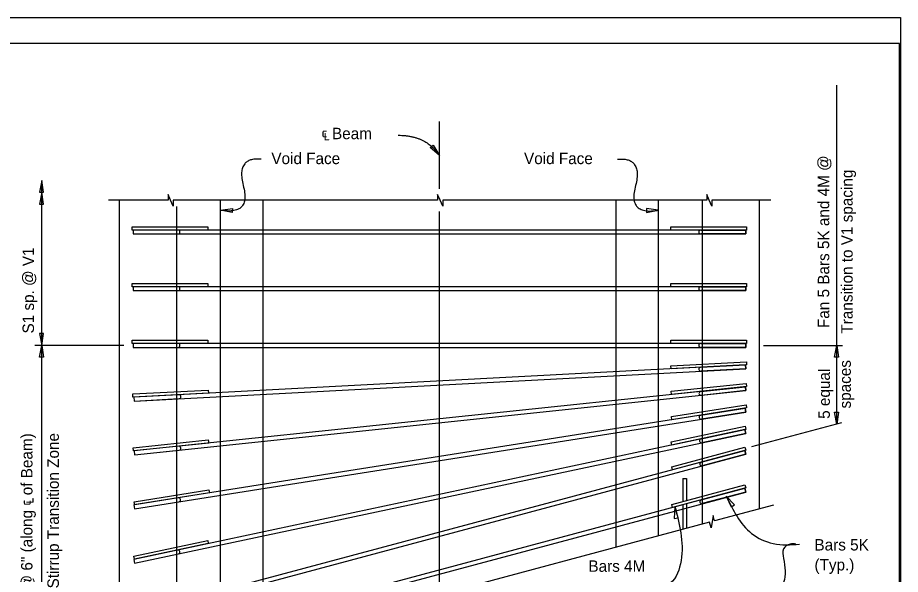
# Model space of a CAD drawing. Extents: x 0 to 30.8, y 0 to 19.8.
# Drawn here: x 19.12 to 30.8, y 12.43 to 19.8 of the extents above; entities that cross this region are included whole.
import ezdxf

# ---------------------------------------------------------------- set-up
doc = ezdxf.new("R2010")
doc.units = 0
for name, color, linetype in [('ActivePts-ConstElements', 7, 'Continuous'), ('BeamConc', 7, 'Continuous'), ('BeamConc_h', 7, 'Continuous'), ('CL_Major', 7, 'Continuous'), ('Dimension', 7, 'Continuous'), ('Miscellaneous1', 7, 'Continuous'), ('Rebar', 7, 'Continuous'), ('Rebar_h', 7, 'Continuous'), ('TextStructures', 7, 'Continuous')]:
    doc.layers.add(name, color=color, linetype=linetype)

msp = doc.modelspace()

# ---------------------------------------------------------------- linework, layer by layer
at = {"layer": 'ActivePts-ConstElements'}
msp.add_lwpolyline([(0, 0), (30.788, 0), (30.788, 19.46), (0, 19.46)], close=True, dxfattribs=at)
at = {"layer": 'BeamConc'}
for p, q in [((20.473, 11.032), (20.473, 17.385)), ((21.807, 11.389), (21.807, 17.385)), ((27.598, 17.385), (27.598, 12.947)), ((28.932, 17.385), (28.932, 13.298))]:
    msp.add_line(p, q, dxfattribs=at)
at = {"layer": 'BeamConc_h'}
for p, q in [((21.223, 17.303), (21.223, 11.233)), ((22.369, 17.385), (22.369, 11.54)), ((27.036, 17.385), (27.036, 12.79)), ((28.182, 13.097), (28.182, 17.385))]:
    msp.add_line(p, q, dxfattribs=at)
at = {"layer": 'CL_Major'}
for p, q in [((24.702, 17.537), (24.702, 18.427)), ((24.702, 12.302), (24.702, 17.235))]:
    msp.add_line(p, q, dxfattribs=at)
at = {"layer": 'Dimension'}
for p, q in [((29.958, 14.423), (29.958, 18.908)), ((20.527, 15.464), (19.35, 15.464)), ((28.989, 15.464), (30.034, 15.464)), ((30.022, 14.441), (28.83, 14.121))]:
    msp.add_line(p, q, dxfattribs=at)
for points in [[(24.702, 17.978), (24.581, 18.08), (24.621, 18.114)], [(19.442, 17.646), (19.415, 17.49), (19.468, 17.49)], [(19.442, 17.49), (19.415, 17.334), (19.468, 17.334)], [(21.807, 17.252), (21.964, 17.274), (21.962, 17.221)], [(27.598, 17.252), (27.441, 17.274), (27.443, 17.221)], [(19.442, 15.464), (19.468, 15.62), (19.415, 15.62)], [(19.442, 15.464), (19.468, 15.308), (19.415, 15.308)], [(29.958, 15.464), (29.984, 15.308), (29.931, 15.308)], [(29.958, 14.423), (29.931, 14.58), (29.984, 14.58)], [(28.496, 13.47), (28.562, 13.326), (28.606, 13.356)], [(27.817, 13.333), (27.809, 13.175), (27.861, 13.181)]]:
    msp.add_lwpolyline(points, close=True, dxfattribs=at)
for points in [[(19.442, 11.509), (19.442, 17.646)], [(21.694, 17.385), (21.182, 17.385), (21.182, 17.307), (21.148, 17.385), (21.114, 17.462), (21.114, 17.385), (20.325, 17.385)], [(27.522, 17.385), (24.746, 17.385), (24.746, 17.307), (24.712, 17.385), (24.678, 17.462), (24.678, 17.385), (21.694, 17.385)], [(29.086, 17.385), (28.307, 17.385), (28.307, 17.307), (28.273, 17.385), (28.239, 17.462), (28.239, 17.385), (27.522, 17.385)], [(29.121, 13.349), (28.342, 13.141), (28.322, 13.215), (28.31, 13.132), (28.297, 13.048), (28.277, 13.123), (26.782, 12.723)], [(26.782, 12.723), (24.745, 12.177), (24.725, 12.252), (24.713, 12.168), (24.705, 12.116)]]:
    msp.add_lwpolyline(points, dxfattribs=at)
for points in [[(24.159, 18.244), (24.523, 18.244), (24.702, 17.979)], [(22.345, 17.927), (22.008, 17.958), (22.211, 17.182), (21.807, 17.252)], [(27.06, 17.927), (27.397, 17.958), (27.194, 17.182), (27.598, 17.252)]]:
    msp.add_open_spline(points, degree=2, dxfattribs=at)
for points in [[(28.496, 13.47), (28.833, 12.976), (29.118, 12.842), (29.467, 12.833)], [(27.817, 13.338), (27.899, 12.616), (27.755, 12.319), (27.582, 12.253), (27.422, 12.253)], [(29.419, 12.835), (29.343, 12.835), (29.255, 12.772), (29.255, 12.645), (29.255, 12.328), (29.157, 12.174), (29.014, 12.076), (28.873, 12.034), (28.735, 11.996)]]:
    msp.add_spline(points, degree=3, dxfattribs=at)
at = {"layer": 'Miscellaneous1'}
msp.add_lwpolyline([(0, 19.8), (30.8, 19.8), (30.8, 0), (0, 0)], close=True, dxfattribs=at)
at = {"layer": 'Rebar'}
for p, q in [((20.64, 17.032), (21.64, 17.032)), ((20.64, 16.99), (20.64, 17.032)), ((21.64, 16.99), (20.64, 16.99)), ((21.245, 16.99), (20.651, 16.99)), ((20.651, 16.99), (20.651, 16.938)), ((20.651, 16.938), (21.245, 16.938)), ((21.64, 17.032), (21.64, 16.99)), ((27.765, 17.032), (28.765, 17.032)), ((27.765, 16.99), (27.765, 17.032)), ((28.765, 16.99), (27.765, 16.99)), ((28.16, 16.99), (28.754, 16.99)), ((28.754, 16.938), (28.16, 16.938)), ((28.754, 16.99), (28.754, 16.938)), ((28.765, 17.032), (28.765, 16.99)), ((20.64, 16.282), (21.64, 16.282)), ((20.64, 16.24), (20.64, 16.282)), ((21.64, 16.24), (20.64, 16.24)), ((21.245, 16.24), (20.651, 16.24)), ((20.651, 16.24), (20.651, 16.188)), ((21.64, 16.282), (21.64, 16.24)), ((27.765, 16.282), (28.765, 16.282)), ((27.765, 16.24), (27.765, 16.282)), ((28.765, 16.24), (27.765, 16.24)), ((28.16, 16.24), (28.754, 16.24)), ((28.754, 16.24), (28.754, 16.188)), ((28.765, 16.282), (28.765, 16.24)), ((20.651, 16.188), (21.245, 16.188)), ((28.754, 16.188), (28.16, 16.188)), ((20.64, 15.532), (21.64, 15.532)), ((20.64, 15.49), (20.64, 15.532)), ((21.64, 15.532), (21.64, 15.49)), ((27.765, 15.532), (28.765, 15.532)), ((27.765, 15.49), (27.765, 15.532)), ((28.765, 15.532), (28.765, 15.49)), ((21.64, 15.49), (20.64, 15.49)), ((21.245, 15.49), (20.651, 15.49)), ((20.651, 15.49), (20.651, 15.438)), ((20.651, 15.438), (21.245, 15.438)), ((28.765, 15.49), (27.765, 15.49)), ((28.16, 15.49), (28.754, 15.49)), ((28.754, 15.438), (28.16, 15.438)), ((28.754, 15.49), (28.754, 15.438)), ((27.765, 15.195), (28.764, 15.247)), ((27.767, 15.153), (27.765, 15.195)), ((28.766, 15.205), (27.767, 15.153)), ((28.16, 15.174), (28.753, 15.205)), ((28.753, 15.205), (28.756, 15.153)), ((28.764, 15.247), (28.766, 15.205)), ((28.756, 15.153), (28.163, 15.122)), ((27.767, 14.856), (28.761, 14.96)), ((28.761, 14.96), (28.766, 14.919)), ((20.646, 14.821), (21.645, 14.873)), ((21.647, 14.831), (20.648, 14.779)), ((21.645, 14.873), (21.647, 14.831)), ((27.771, 14.814), (27.767, 14.856)), ((28.766, 14.919), (27.771, 14.814)), ((28.159, 14.855), (28.75, 14.917)), ((28.755, 14.865), (28.165, 14.803)), ((28.75, 14.917), (28.755, 14.865)), ((20.648, 14.779), (20.646, 14.821)), ((21.256, 14.811), (20.663, 14.78)), ((20.663, 14.78), (20.665, 14.728)), ((20.665, 14.728), (21.259, 14.759)), ((27.771, 14.521), (28.759, 14.677)), ((28.765, 14.636), (27.778, 14.48)), ((28.16, 14.54), (28.747, 14.633)), ((28.747, 14.633), (28.755, 14.582)), ((28.759, 14.677), (28.765, 14.636)), ((27.778, 14.48), (27.771, 14.521)), ((28.755, 14.582), (28.168, 14.489)), ((27.77, 14.186), (28.749, 14.394)), ((28.749, 14.394), (28.757, 14.353)), ((28.757, 14.353), (27.779, 14.145)), ((28.164, 14.227), (28.745, 14.351)), ((28.756, 14.3), (28.175, 14.176)), ((28.745, 14.351), (28.756, 14.3)), ((20.652, 14.109), (21.646, 14.214)), ((21.651, 14.172), (20.656, 14.068)), ((21.254, 14.129), (20.664, 14.067)), ((21.646, 14.214), (21.651, 14.172)), ((27.779, 14.145), (27.77, 14.186)), ((20.656, 14.068), (20.652, 14.109)), ((20.664, 14.067), (20.669, 14.015)), ((20.669, 14.015), (21.26, 14.077)), ((27.777, 13.859), (28.743, 14.118)), ((28.754, 14.078), (27.788, 13.819)), ((28.167, 13.92), (28.741, 14.074)), ((28.754, 14.024), (28.18, 13.87)), ((28.741, 14.074), (28.754, 14.024)), ((28.743, 14.118), (28.754, 14.078)), ((27.788, 13.819), (27.777, 13.859)), ((27.921, 13.703), (27.973, 13.703)), ((27.921, 13.703), (27.921, 13.398)), ((27.973, 13.703), (27.973, 13.412)), ((20.665, 13.396), (21.653, 13.552)), ((21.653, 13.552), (21.66, 13.511)), ((27.777, 13.359), (28.743, 13.618)), ((28.754, 13.578), (27.788, 13.319)), ((28.167, 13.42), (28.741, 13.574)), ((28.741, 13.574), (28.754, 13.524)), ((28.743, 13.618), (28.754, 13.578)), ((21.249, 13.446), (20.662, 13.353)), ((21.66, 13.511), (20.672, 13.354)), ((28.754, 13.524), (28.18, 13.37)), ((20.662, 13.353), (20.671, 13.301)), ((20.672, 13.354), (20.665, 13.396)), ((20.671, 13.301), (21.257, 13.394)), ((27.788, 13.319), (27.777, 13.359)), ((27.921, 13.354), (27.921, 13.028)), ((27.973, 13.368), (27.973, 13.042)), ((20.659, 12.675), (21.638, 12.883)), ((21.638, 12.883), (21.646, 12.842)), ((21.24, 12.755), (20.659, 12.632)), ((21.646, 12.842), (20.668, 12.634)), ((20.668, 12.634), (20.659, 12.675)), ((20.659, 12.632), (20.67, 12.581)), ((20.67, 12.581), (21.251, 12.704))]:
    msp.add_line(p, q, dxfattribs=at)
for centre, start, end in [((21.245, 16.964), 270, 90), ((28.16, 16.964), 90, 270), ((21.245, 16.214), 270, 90), ((28.16, 16.214), 90, 270), ((21.245, 15.464), 270, 90), ((28.16, 15.464), 90, 270), ((28.161, 15.148), 93, 273), ((28.162, 14.829), 96, 276), ((21.257, 14.785), 273, 93), ((28.164, 14.515), 99, 279), ((21.257, 14.103), 276, 96), ((28.169, 14.202), 102, 282), ((28.174, 13.895), 105, 285), ((21.253, 13.42), 279, 99), ((28.174, 13.395), 105, 285), ((21.245, 12.73), 282, 102)]:
    msp.add_arc(centre, 0.026, start, end, dxfattribs=at)
at = {"layer": 'Rebar_h'}
for points in [[(28.754, 16.99), (20.651, 16.99), (20.651, 16.938), (28.754, 16.938)], [(28.754, 16.24), (20.651, 16.24), (20.651, 16.188), (28.754, 16.188)], [(28.754, 15.49), (20.651, 15.49), (20.651, 15.438), (28.754, 15.438)], [(28.753, 15.205), (20.663, 14.78), (20.665, 14.728), (28.756, 15.153)], [(28.75, 14.917), (20.664, 14.067), (20.669, 14.015), (28.755, 14.865)], [(28.747, 14.633), (20.662, 13.353), (20.671, 13.301), (28.755, 14.582)], [(28.745, 14.351), (20.659, 12.632), (20.67, 12.581), (28.756, 14.3)], [(28.741, 14.074), (20.651, 11.906), (20.665, 11.856), (28.754, 14.024)], [(28.741, 13.574), (20.651, 11.406), (20.665, 11.356), (28.754, 13.524)]]:
    msp.add_lwpolyline(points, close=True, dxfattribs=at)

# ---------------------------------------------------------------- texts
at = {"layer": 'Dimension'}
for s, p in [('Bars 5K', (29.664, 12.75)), ('Bars 4M ', (26.674, 12.468)), ('(Typ.)', (29.664, 12.486))]:
    msp.add_text(s, height=0.1512, dxfattribs=at).set_placement(p)
at = {"layer": 'TextStructures'}
for s, p in [('℄ Beam', (23.144, 18.192)), ('Void Face', (22.48, 17.862)), ('Void Face', (25.822, 17.862))]:
    msp.add_text(s, height=0.1512, dxfattribs=at).set_placement(p)
for s, p in [('Fan 5 Bars 5K and 4M @ ', (29.859, 15.693)), ('Transition to V1 spacing', (30.169, 15.62)), ('S1 sp. @ V1 ', (19.34, 15.621)), ('spaces', (30.145, 14.629)), ('5 equal ', (29.868, 14.492)), ('5 sp. @ 6" (along ℄ of Beam)', (19.32, 11.728)), ('Stirrup Transition Zone ', (19.669, 12.248))]:
    msp.add_text(s, height=0.1512, rotation=90, dxfattribs=at).set_placement(p)

doc.saveas('drawing.dxf')
